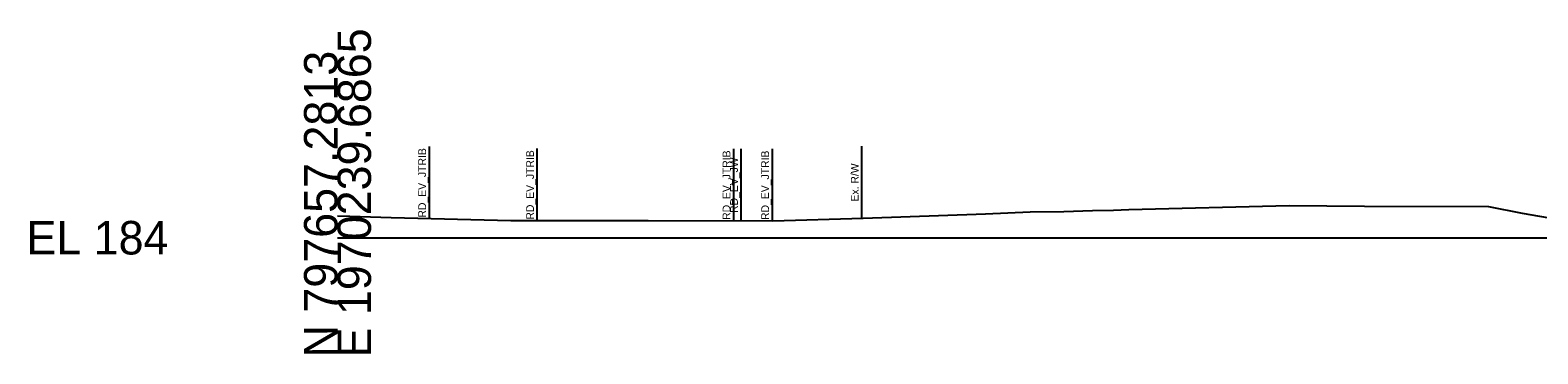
# Model space of a CAD drawing. Extents: x -26 to 303, y -10 to 1532.
# Drawn here: x -25.7 to 100.3, y 990.3 to 1017.3 of the extents above; entities that cross this region are included whole.
import ezdxf

# ---------------------------------------------------------------- set-up
doc = ezdxf.new("R2010")
doc.units = 0
for name, color, linetype in [('RD_GPK_XS_Cell', 7, 'Continuous'), ('RD_XS_ExGround', 7, 'Continuous'), ('RD_XS_ExRW', 7, 'Continuous'), ('RD_XS_EXWetland', 7, 'Continuous')]:
    doc.layers.add(name, color=color, linetype=linetype)

msp = doc.modelspace()

# ---------------------------------------------------------------- linework, layer by layer
at = {"layer": 'RD_GPK_XS_Cell'}
msp.add_line((0, 1000), (150, 1000), dxfattribs=at)
at = {"layer": 'RD_XS_ExGround'}
msp.add_lwpolyline([(0, 1001.82), (1.04, 1001.81), (4.49, 1001.69), (14.5, 1001.45), (18.4, 1001.45), (19.19, 1001.45), (21.05, 1001.45), (22.18, 1001.45), (24.4, 1001.45), (25.96, 1001.43), (36.4, 1001.42), (43.94, 1001.64), (54.16, 1002), (57.89, 1002.15), (60.72, 1002.2), (63.12, 1002.28), (64.86, 1002.3), (66.14, 1002.35), (79.54, 1002.69), (85.86, 1002.63), (96.22, 1002.62), (99.04, 1002.05), (104.99, 1001.03)], dxfattribs=at)
at = {"layer": 'RD_XS_ExRW'}
msp.add_line((43.81, 1007.64), (43.81, 1001.64), dxfattribs=at)
at = {"layer": 'RD_XS_EXWetland'}
for p, q in [((7.65, 1007.62), (7.65, 1001.62)), ((16.67, 1007.45), (16.67, 1001.45)), ((33.09, 1007.42), (33.09, 1001.42)), ((33.72, 1007.42), (33.72, 1001.42)), ((36.32, 1007.42), (36.32, 1001.42))]:
    msp.add_line(p, q, dxfattribs=at)

# ---------------------------------------------------------------- texts
at = {"layer": 'RD_GPK_XS_Cell'}
for s, p in [('E 1970239.6865', (2.8, 990)), ('N 797657.2813', (0, 990))]:
    msp.add_text(s, height=2.8, rotation=90, dxfattribs=at).set_placement(p)
msp.add_text('EL 184', height=2.8, dxfattribs=at).set_placement((-26, 998.6))
at = {"layer": 'RD_XS_ExRW'}
msp.add_text('Ex. R/W ', height=0.65, rotation=90, dxfattribs=at).set_placement((43.56, 1003.02))
at = {"layer": 'RD_XS_EXWetland'}
for s, p in [('RD_EV_JTRIB', (7.4, 1001.68)), ('RD_EV_JTRIB', (16.42, 1001.51)), ('RD_EV_JTRIB', (32.84, 1001.49)), ('RD_EV_JTRIB', (36.07, 1001.48)), ('RD_EV_JW', (33.47, 1002.07))]:
    msp.add_text(s, height=0.65, rotation=90, dxfattribs=at).set_placement(p)

doc.saveas('drawing.dxf')
